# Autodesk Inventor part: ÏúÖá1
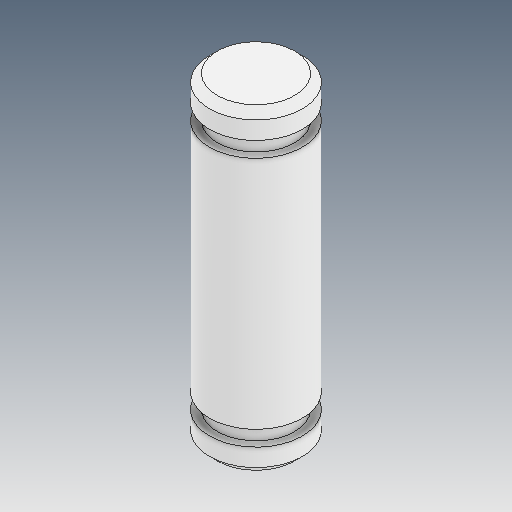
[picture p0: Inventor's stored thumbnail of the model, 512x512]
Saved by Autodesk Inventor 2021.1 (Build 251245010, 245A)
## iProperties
Created: 2021-05
Part Number: ÏúÖá1
Material: Ogólny
Document SubType Name: Modeling
Designer: user
Density: 1 g/cm^3
Appearance: Domyślna
Author: user
Revision Number: ÈÎºÎ
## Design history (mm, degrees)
feature "ÊäÈë1"
node "Bryła1"
